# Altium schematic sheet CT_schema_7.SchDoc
size 251 x 159 mm
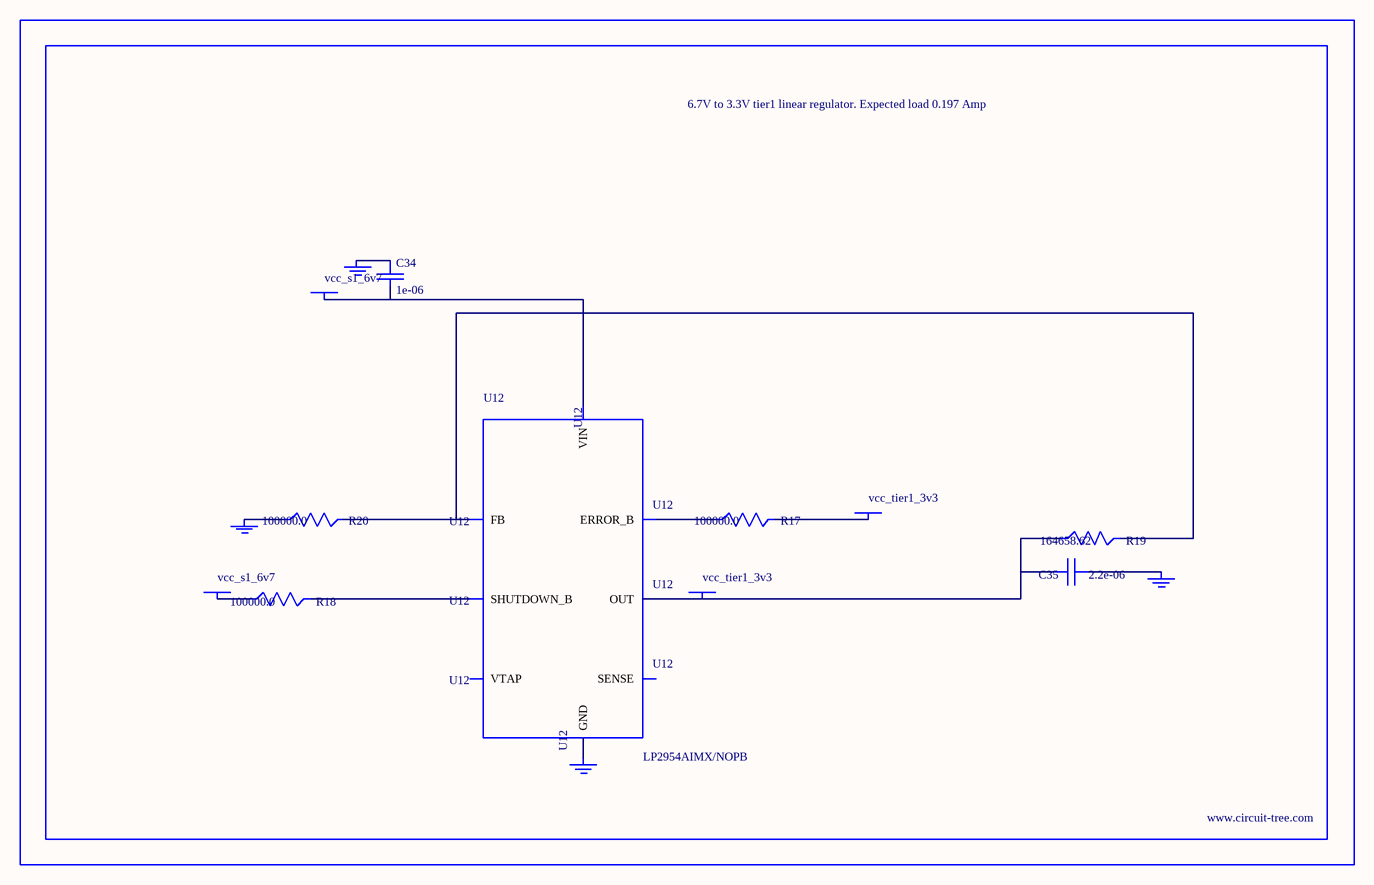
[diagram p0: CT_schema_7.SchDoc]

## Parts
BORDER6  (no value)
C34  1e-06  [EXV-9B]
C35  2.2e-06  [EXV-9B]
GND_INSTANCE_6_0  (no value)
GND_INSTANCE_6_1  (no value)
GND_INSTANCE_6_2  (no value)
GND_INSTANCE_6_3  (no value)
POWER_INSTANCE_6_0  vcc_s1_6v7
POWER_INSTANCE_6_1  vcc_tier1_3v3
POWER_INSTANCE_6_2  vcc_s1_6v7
POWER_INSTANCE_6_3  vcc_tier1_3v3
R17  100000.0  [R0603]
R18  100000.0  [R0603]
R19  164658.62  [R0603]
R20  100000.0  [R0603]
U12  LP2954AIMX/NOPB  [LP2954]

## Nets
NetC34_1: C34.1 GND_INSTANCE_6_2.0(GND)
NetC34_2: C34.2 POWER_INSTANCE_6_2.0(PWR) U12.8(VIN)
NetC35_1: C35.1 GND_INSTANCE_6_0.0(GND)
NetC35_2: C35.2 POWER_INSTANCE_6_3.0(PWR) R19.1 U12.1(OUT)
NetGND_INSTANCE_6_1_0: GND_INSTANCE_6_1.0(GND) R20.1
NetGND_INSTANCE_6_3_0: GND_INSTANCE_6_3.0(GND) U12.4(GND)
NetPOWER_INSTANCE_6_0_0: POWER_INSTANCE_6_0.0(PWR) R18.1
NetPOWER_INSTANCE_6_1_0: POWER_INSTANCE_6_1.0(PWR) R17.2
NetR17_1: R17.1 U12.5(ERROR_B)
NetR18_2: R18.2 U12.3(SHUTDOWN_B)
NetR19_2: R19.2 R20.2 U12.7(FB)

Not connected (* = marked no-connect by the designer): U12 2(SENSE) 6(VTAP)

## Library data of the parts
BORDER6 = BORDER_PAGE6
C34 = EDK105M050A9BAA
C35 = EDK225M050A9BAA
GND_INSTANCE_6_0-GND_INSTANCE_6_3 = GND
POWER_INSTANCE_6_0-POWER_INSTANCE_6_3 = PWR
R17 R18 R20 = RC0603JR-07100KL
R19 = R19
